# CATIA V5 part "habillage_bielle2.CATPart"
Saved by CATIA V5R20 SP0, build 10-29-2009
Part number: habillage_bielle2
Bounding box of the stored display mesh (mm): x 0 to 10, y 340 to 360, z -60 to 10
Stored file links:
  C:\Users\Noëllie\Documents\IFMA\2A\S3\IAO\Projet Artobolevski\Catia\habillage_bielle2.CATPart
  C:\Users\Noëllie\Documents\IFMA\2A\S3\IAO\Projet Artobolevski\Catia\assemblage_balance.CATProduct
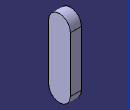
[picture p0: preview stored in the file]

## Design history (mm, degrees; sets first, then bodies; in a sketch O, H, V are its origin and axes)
Set1
  Point1 "C2": linked copy from another document
  Point2 "B2d": linked copy from another document
Body1 (main body)
  Sketch1 on yz-plane, origin (0, 0, 0), H (0, 1, 0), V (0, 0, 1)
    line L1 (340, 0) -> (340, -50)
    point P1 (340, 0)
    line L2 (360, 0) -> (360, -50)
    point P3 (360, 0)
    arc A1 centre (350, 0) radius 10 from (340, 0) to (360, 0) cw
    point P5 (350, 0)
    arc A2 centre (350, -50) radius 10 from (340, -50) to (360, -50) ccw
    point P6 (350, -50)
    reference projected point E1 (350, -50) from Point1
    reference projected point E2 (350, 0) from Point2
    distance L1 L2 = 20
    coincidence: P1 H, P3 H, P6 E1, E2 P5
    vertical: L1 V, L2 V
    tangency: A1 L2, A2 L2
  Pad1: profile Sketch1, direction (1, 0, 0), length 10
